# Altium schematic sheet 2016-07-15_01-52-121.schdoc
size 295 x 142 mm; SheetNumber: 1; SheetTotal: 1
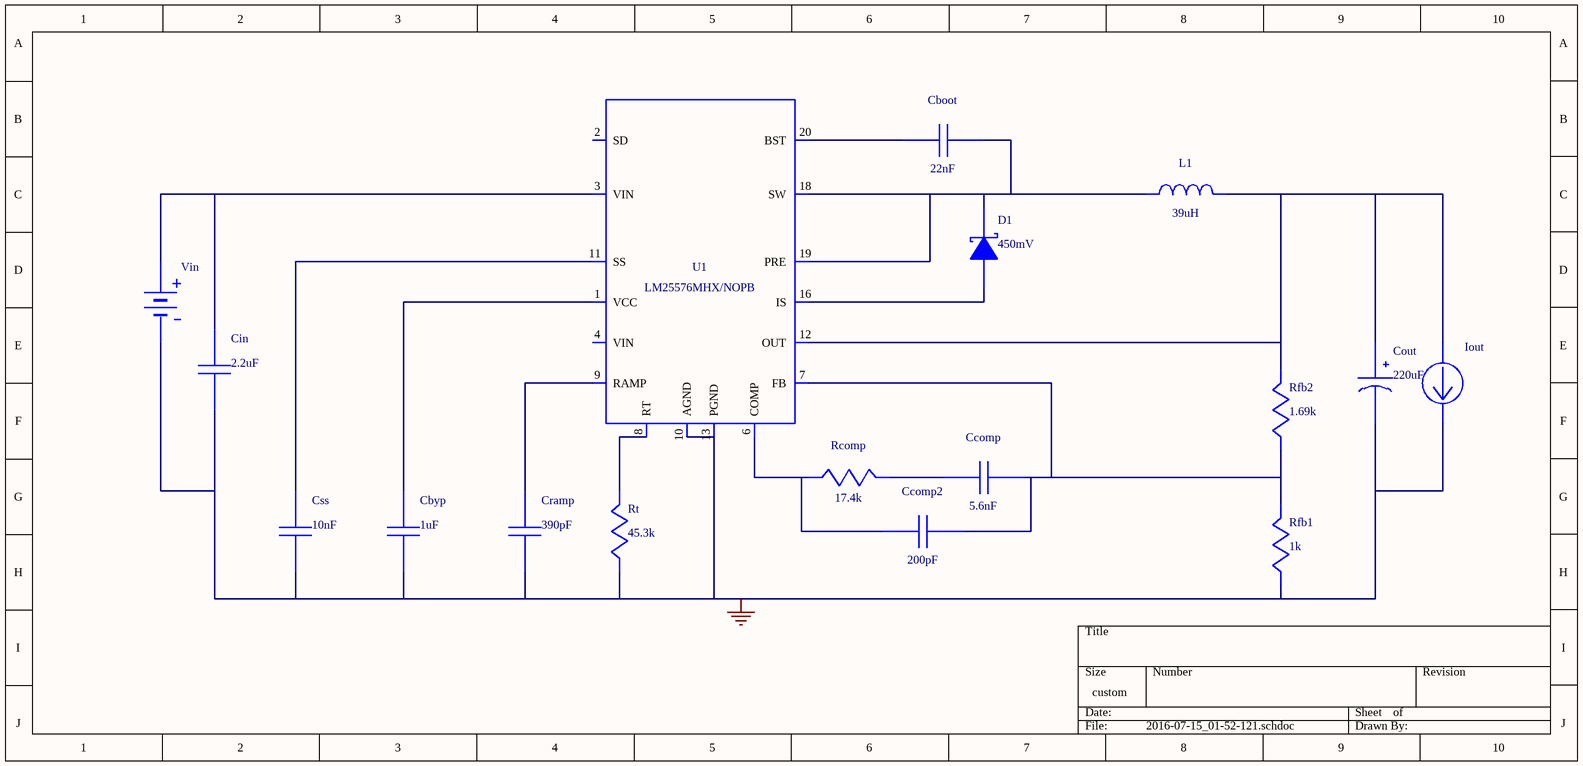
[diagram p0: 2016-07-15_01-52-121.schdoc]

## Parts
Cboot  value 22nF  (hidden comment: C0603C223K3RACTU)
Cbyp  value 1uF  (hidden comment: GRM188R61E105KA12D)
Ccomp  value 5.6nF  (hidden comment: GRM188R71E562KA01D)
Ccomp2  value 200pF  (hidden comment: CL21C201JBANNNC)
Cin  value 2.2uF  (hidden comment: GRM31CR71H225KA88L)
Cout  value 220uF  (hidden comment: 6SVPE220MW)
Cramp  value 390pF  (hidden comment: CC0805KRX7R9BB391)
Css  value 10nF  (hidden comment: GRM188R71E103KA01D)
D1  value 450mV  (hidden comment: B340LA-13-F)
Iout  WB_CURRENT_LOAD  (value not drawn)
L1  value 39uH  (hidden comment: PM2120-390K-RC)
Rcomp  value 17.4k  (hidden comment: CRCW060317K4FKEA)
Rfb1  value 1k  (hidden comment: CRCW06031K00FKEA)
Rfb2  value 1.69k  (hidden comment: ERJ-6ENF1691V)
Rt  value 45.3k  (hidden comment: CRCW060345K3FKEA)
U1  LM25576MHX/NOPB
Vin  WB_BATTERY  (value not drawn)

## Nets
0: Cbyp.2 Cin.2 Cout.2(-) Cramp.2 Css.2 Iout.2(-) Rfb1.2 Rt.2 U1.10(AGND) U1.13(PGND) U1.14(PGND) U1.21(DAP) Vin.2(-)
NetCboot_1: Cboot.1 D1.1(K) L1.1 U1.17(SW) U1.18(SW) U1.19(PRE)
NetCboot_2: Cboot.2 U1.20(BST)
NetCbyp_1: Cbyp.1 U1.1(VCC)
NetCcomp2_2: Ccomp2.2 Rcomp.2 U1.6(COMP)
NetCcomp_1: Ccomp.1 Ccomp2.1 Rfb1.1 Rfb2.2 U1.7(FB)
NetCcomp_2: Ccomp.2 Rcomp.1
NetCin_1: Cin.1 U1.3(VIN) Vin.1(+)
NetCout_1: Cout.1(+) Iout.1(+) L1.2 Rfb2.1 U1.12(OUT)
NetCramp_1: Cramp.1 U1.9(RAMP)
NetCss_1: Css.1 U1.11(SS)
NetD1_2: D1.2(A) U1.15(IS) U1.16(IS)
NetRt_1: Rt.1 U1.8(RT)
NetU1_4: U1.4(VIN) U1.5(SYNC)

Not connected (* = marked no-connect by the designer): U1 2(SD)

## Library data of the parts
Cboot = C0603C223K3RACTU: Manufacturer Name: Kemet
Cbyp = GRM188R61E105KA12D: GRM188R61E105KA1; Manufacturer Name: MuRata
Ccomp = GRM188R71E562KA01D: GRM188R71E562KA0; Manufacturer Name: MuRata
Ccomp2 = CL21C201JBANNNC: Manufacturer Name: Samsung Electro-Mechanics
Cin = GRM31CR71H225KA88L: GRM31CR71H225KA8; Manufacturer Name: MuRata
Cout = 6SVPE220MW: Manufacturer Name: Panasonic
Cramp = CC0805KRX7R9BB391: CC0805KRX7R9BB39; Manufacturer Name: Yageo America
Css = GRM188R71E103KA01D: GRM188R71E103KA0; Manufacturer Name: MuRata
D1 = B340LA-13-F: Manufacturer Name: Diodes Inc.
L1 = PM2120-390K-RC: Manufacturer Name: Bourns
Rcomp = CRCW060317K4FKEA: Manufacturer Name: Vishay-Dale
Rfb1 = CRCW06031K00FKEA: Manufacturer Name: Vishay-Dale
Rfb2 = ERJ-6ENF1691V: Manufacturer Name: Panasonic
Rt = CRCW060345K3FKEA: Manufacturer Name: Vishay-Dale
U1 = LM25576MHX/NOPB: Manufacturer Name: Texas Instruments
